(* Logix 5000 project; controller AMCI_3202_AOP_AOI_sample_RSLogix_V28 vendor 1 type 14 code 92 rev 28.11; software revision 28.00; part 2 of 3 *)
(* tags used below, declared in another part *)
   Manual_Move_CW_occurring : BOOL;
(* AMCI_3202_AOP_Manual_Move_CW, continued *)

ROUTINE Logic   (* ladder *)
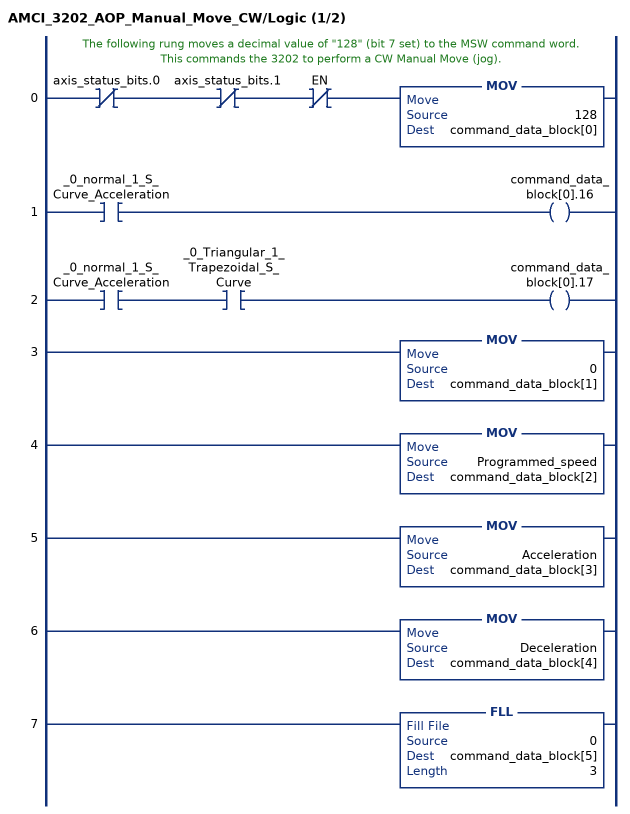
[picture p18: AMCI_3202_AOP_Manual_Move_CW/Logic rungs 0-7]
   // The following rung moves a decimal value of "128" (bit 7 set) to the MSW command word.  This commands the 3202 to perform a CW Manual Move (jog).
   0: XIO(axis_status_bits.0)XIO(axis_status_bits.1)XIO(EN)MOV(128,command_data_block[0]);
   1: XIC(_0_normal_1_S_Curve_Acceleration)OTE(command_data_block[0].16);
   2: XIC(_0_normal_1_S_Curve_Acceleration)XIC(_0_Triangular_1_Trapezoidal_S_Curve)OTE(command_data_block[0].17);
   3: MOV(0,command_data_block[1]);
   4: MOV(Programmed_speed,command_data_block[2]);
   5: MOV(Acceleration,command_data_block[3]);
   6: MOV(Deceleration,command_data_block[4]);
   7: FLL(0,command_data_block[5],3);
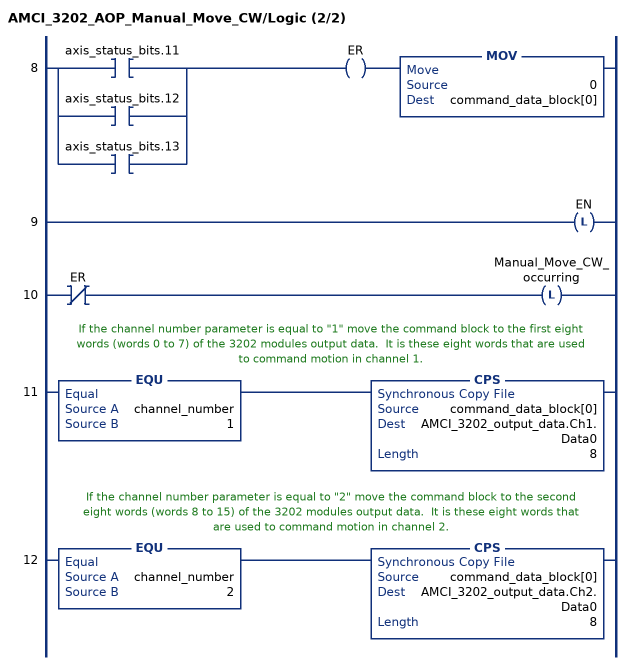
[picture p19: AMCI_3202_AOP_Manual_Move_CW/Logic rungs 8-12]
   8: [XIC(axis_status_bits.11) ,XIC(axis_status_bits.12) ,XIC(axis_status_bits.13) ]OTE(ER)MOV(0,command_data_block[0]);
   9: OTL(EN);
   10: XIO(ER)OTL(Manual_Move_CW_occurring);
   // If the channel number parameter is equal to "1" move the command block to the first eight words (words 0 to 7) of the 3202 modules output data.  It is these eight words that are used to command motion in channel 1.
   11: EQU(channel_number,1)CPS(command_data_block[0],AMCI_3202_output_data.Ch1.Data0,8);
   // If the channel number parameter is equal to "2" move the command block to the second eight words (words 8 to 15) of the 3202 modules output data.  It is these eight words that are used to command motion in channel 2.
   12: EQU(channel_number,2)CPS(command_data_block[0],AMCI_3202_output_data.Ch2.Data0,8);
END_ROUTINE
END_ADD_ON_INSTRUCTION

ADD_ON_INSTRUCTION AMCI_3202_AOP_Preset   (* revision 1.0, vendor AMCI, ExecuteEnableInFalse *)
VAR_INPUT
   axis_status_bits : INT; {required}
   channel_number : INT; {required}
   Target_Position : DINT; {required}
END_VAR
VAR_IN_OUT
   AMCI_3202_output_data : AM:1756_3202:O:0; {required}
END_VAR
VAR_OUTPUT
   EN : BOOL; {access Read Only, visible}
   ER : BOOL; {access Read Only, visible}
END_VAR
VAR
   command_data_block : DINT[8]; {access None}
END_VAR

ROUTINE EnableInFalse   (* ladder *)
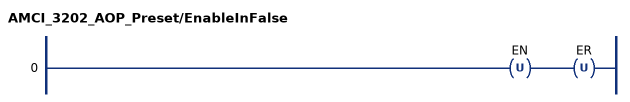
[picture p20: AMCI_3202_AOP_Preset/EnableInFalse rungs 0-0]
   0: OTU(EN)OTU(ER);
END_ROUTINE

ROUTINE Logic   (* ladder *)
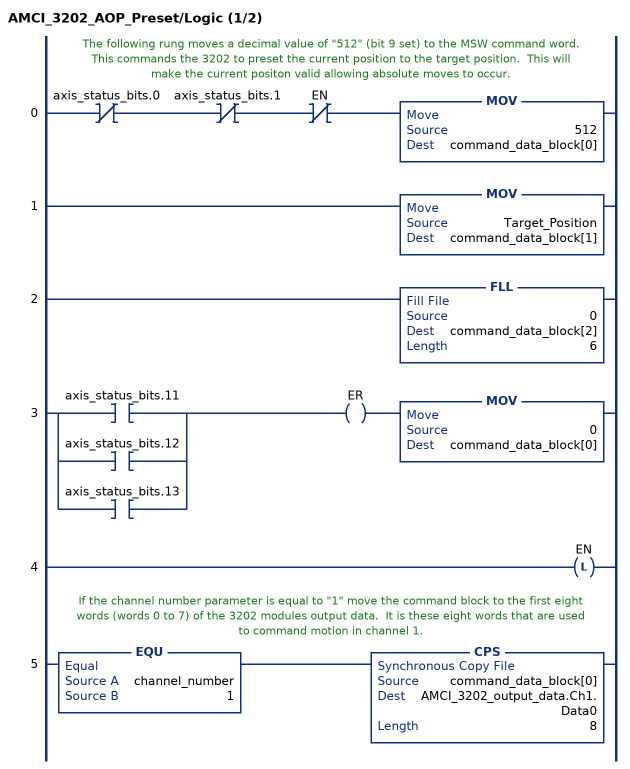
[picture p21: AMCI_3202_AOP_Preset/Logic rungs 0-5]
   // The following rung moves a decimal value of "512" (bit 9 set) to the MSW command word.  This commands the 3202 to preset the current position to the target position.  This will make the current positon valid allowing absolute moves to occur.
   0: XIO(axis_status_bits.0)XIO(axis_status_bits.1)XIO(EN)MOV(512,command_data_block[0]);
   1: MOV(Target_Position,command_data_block[1]);
   2: FLL(0,command_data_block[2],6);
   3: [XIC(axis_status_bits.11) ,XIC(axis_status_bits.12) ,XIC(axis_status_bits.13) ]OTE(ER)MOV(0,command_data_block[0]);
   4: OTL(EN);
   // If the channel number parameter is equal to "1" move the command block to the first eight words (words 0 to 7) of the 3202 modules output data.  It is these eight words that are used to command motion in channel 1.
   5: EQU(channel_number,1)CPS(command_data_block[0],AMCI_3202_output_data.Ch1.Data0,8);
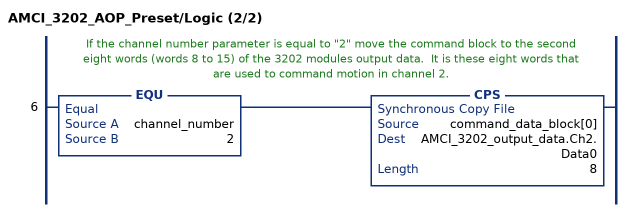
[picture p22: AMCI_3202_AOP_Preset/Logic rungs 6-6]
   // If the channel number parameter is equal to "2" move the command block to the second eight words (words 8 to 15) of the 3202 modules output data.  It is these eight words that are used to command motion in channel 2.
   6: EQU(channel_number,2)CPS(command_data_block[0],AMCI_3202_output_data.Ch2.Data0,8);
END_ROUTINE
END_ADD_ON_INSTRUCTION

ADD_ON_INSTRUCTION AMCI_3202_AOP_Preset_Encoder   (* revision 1.0, vendor AMCI, ExecuteEnableInFalse *)
VAR_INPUT
   axis_status_bits : INT; {required}
   channel_number : INT; {required}
   Target_Position : DINT; {required}
END_VAR
VAR_IN_OUT
   AMCI_3202_output_data : AM:1756_3202:O:0; {required}
END_VAR
VAR_OUTPUT
   EN : BOOL; {access Read Only, visible}
   ER : BOOL; {access Read Only, visible}
END_VAR
VAR
   command_data_block : DINT[8]; {access None}
END_VAR

ROUTINE EnableInFalse   (* ladder *)
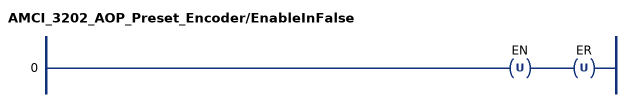
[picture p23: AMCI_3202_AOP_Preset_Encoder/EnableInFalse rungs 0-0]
   0: OTU(EN)OTU(ER);
END_ROUTINE

ROUTINE Logic   (* ladder *)
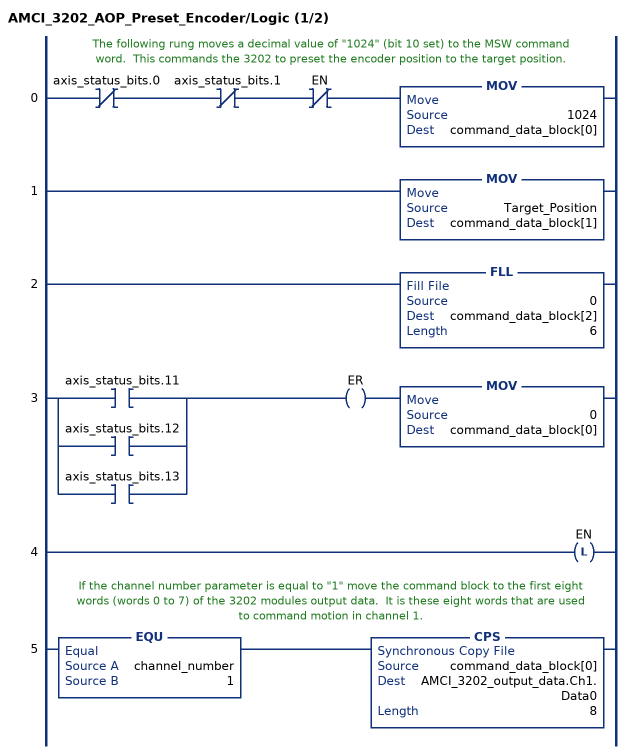
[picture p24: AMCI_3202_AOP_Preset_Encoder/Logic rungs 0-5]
   // The following rung moves a decimal value of "1024" (bit 10 set) to the MSW command word.  This commands the 3202 to preset the encoder position to the target position.
   0: XIO(axis_status_bits.0)XIO(axis_status_bits.1)XIO(EN)MOV(1024,command_data_block[0]);
   1: MOV(Target_Position,command_data_block[1]);
   2: FLL(0,command_data_block[2],6);
   3: [XIC(axis_status_bits.11) ,XIC(axis_status_bits.12) ,XIC(axis_status_bits.13) ]OTE(ER)MOV(0,command_data_block[0]);
   4: OTL(EN);
   // If the channel number parameter is equal to "1" move the command block to the first eight words (words 0 to 7) of the 3202 modules output data.  It is these eight words that are used to command motion in channel 1.
   5: EQU(channel_number,1)CPS(command_data_block[0],AMCI_3202_output_data.Ch1.Data0,8);
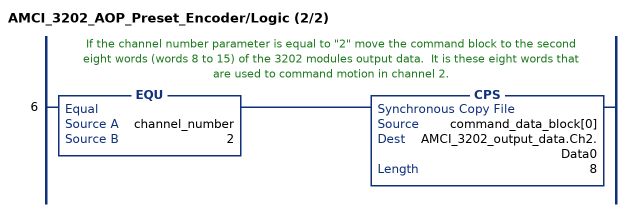
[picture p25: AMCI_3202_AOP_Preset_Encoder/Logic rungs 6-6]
   // If the channel number parameter is equal to "2" move the command block to the second eight words (words 8 to 15) of the 3202 modules output data.  It is these eight words that are used to command motion in channel 2.
   6: EQU(channel_number,2)CPS(command_data_block[0],AMCI_3202_output_data.Ch2.Data0,8);
END_ROUTINE
END_ADD_ON_INSTRUCTION

ADD_ON_INSTRUCTION AMCI_3202_AOP_Relative_Move   (* revision 1.0, vendor AMCI, ExecuteEnableInFalse *)
VAR_INPUT
   axis_status_bits : INT; {required}
   channel_number : INT; {required}
   _0_normal_1_S_Curve_Acceleration : BOOL;
   _0_Triangular_1_Trapezoidal_S_Curve : BOOL;
   _0_Target_Position_1_Encoder_Move : BOOL;
   Target_Position : DINT; {required}
   Programmed_speed : DINT; {required}
   Acceleration : DINT; {required}
   Deceleration : DINT; {required}
END_VAR
VAR_IN_OUT
   AMCI_3202_output_data : AM:1756_3202:O:0; {required}
END_VAR
VAR_OUTPUT
   EN : BOOL; {access Read Only, visible}
   ER : BOOL; {access Read Only, visible}
END_VAR
VAR
   command_data_block : DINT[8]; {access None}
END_VAR

ROUTINE EnableInFalse   (* ladder *)
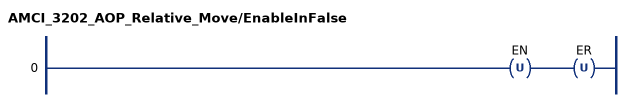
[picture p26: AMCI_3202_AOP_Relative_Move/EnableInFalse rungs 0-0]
   0: OTU(EN)OTU(ER);
END_ROUTINE

ROUTINE Logic   (* ladder *)
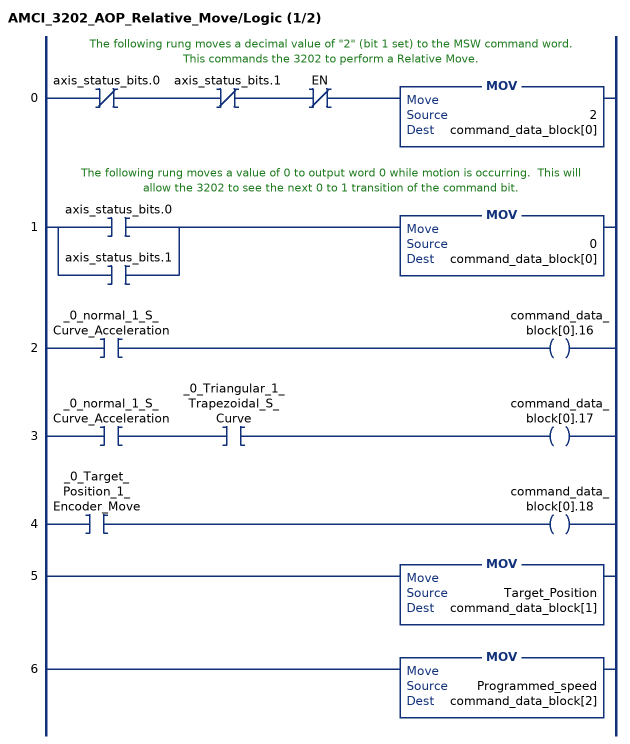
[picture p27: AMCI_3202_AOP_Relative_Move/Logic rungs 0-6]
   // The following rung moves a decimal value of "2" (bit 1 set) to the MSW command word.  This commands the 3202 to perform a Relative Move.
   0: XIO(axis_status_bits.0)XIO(axis_status_bits.1)XIO(EN)MOV(2,command_data_block[0]);
   // The following rung moves a value of 0 to output word 0 while motion is occurring.  This will allow the 3202 to see the next 0 to 1 transition of the command bit.
   1: [XIC(axis_status_bits.0) ,XIC(axis_status_bits.1) ]MOV(0,command_data_block[0]);
   2: XIC(_0_normal_1_S_Curve_Acceleration)OTE(command_data_block[0].16);
   3: XIC(_0_normal_1_S_Curve_Acceleration)XIC(_0_Triangular_1_Trapezoidal_S_Curve)OTE(command_data_block[0].17);
   4: XIC(_0_Target_Position_1_Encoder_Move)OTE(command_data_block[0].18);
   5: MOV(Target_Position,command_data_block[1]);
   6: MOV(Programmed_speed,command_data_block[2]);
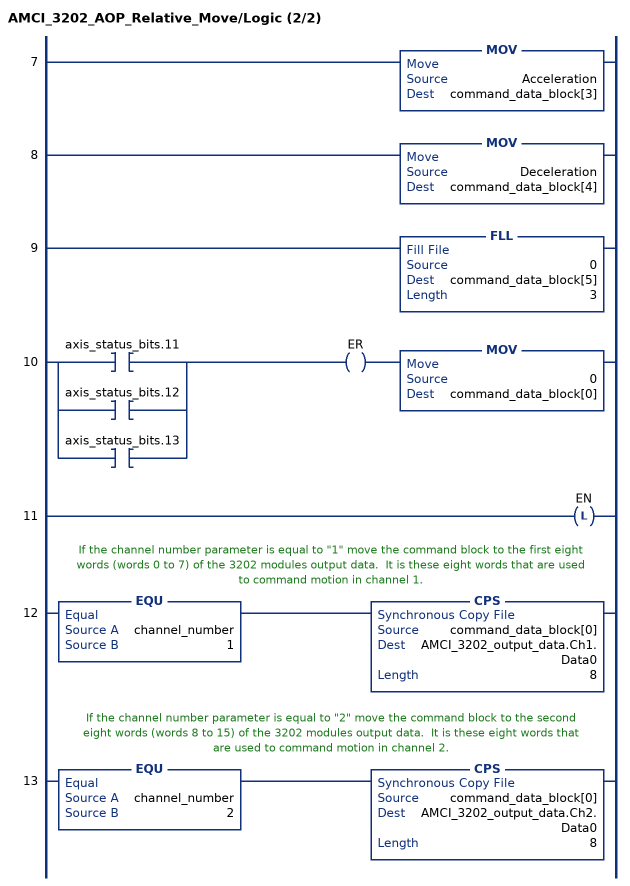
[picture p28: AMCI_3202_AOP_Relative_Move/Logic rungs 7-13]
   7: MOV(Acceleration,command_data_block[3]);
   8: MOV(Deceleration,command_data_block[4]);
   9: FLL(0,command_data_block[5],3);
   10: [XIC(axis_status_bits.11) ,XIC(axis_status_bits.12) ,XIC(axis_status_bits.13) ]OTE(ER)MOV(0,command_data_block[0]);
   11: OTL(EN);
   // If the channel number parameter is equal to "1" move the command block to the first eight words (words 0 to 7) of the 3202 modules output data.  It is these eight words that are used to command motion in channel 1.
   12: EQU(channel_number,1)CPS(command_data_block[0],AMCI_3202_output_data.Ch1.Data0,8);
   // If the channel number parameter is equal to "2" move the command block to the second eight words (words 8 to 15) of the 3202 modules output data.  It is these eight words that are used to command motion in channel 2.
   13: EQU(channel_number,2)CPS(command_data_block[0],AMCI_3202_output_data.Ch2.Data0,8);
END_ROUTINE
END_ADD_ON_INSTRUCTION

ADD_ON_INSTRUCTION AMCI_3202_AOP_Reset_Errors   (* revision 1.0, vendor AMCI, ExecuteEnableInFalse *)
VAR_INPUT
   axis_status_bits : INT; {required}
   channel_number : INT; {required}
END_VAR
VAR_OUTPUT
   EN : BOOL; {access Read Only, visible}
END_VAR
VAR_IN_OUT
   AMCI_3202_output_data : AM:1756_3202:O:0; {required}
END_VAR
VAR
   command_data_block : DINT[8]; {access None}
END_VAR

ROUTINE EnableInFalse   (* ladder *)
END_ROUTINE

ROUTINE Logic   (* ladder *)
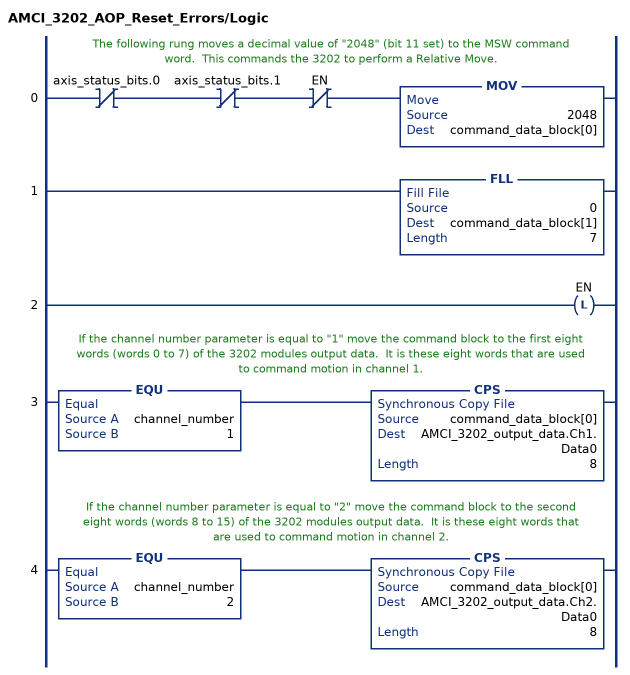
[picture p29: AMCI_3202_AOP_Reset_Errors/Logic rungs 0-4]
   // The following rung moves a decimal value of "2048" (bit 11 set) to the MSW command word.  This commands the 3202 to perform a Relative Move.
   0: XIO(axis_status_bits.0)XIO(axis_status_bits.1)XIO(EN)MOV(2048,command_data_block[0]);
   1: FLL(0,command_data_block[1],7);
   2: OTL(EN);
   // If the channel number parameter is equal to "1" move the command block to the first eight words (words 0 to 7) of the 3202 modules output data.  It is these eight words that are used to command motion in channel 1.
   3: EQU(channel_number,1)CPS(command_data_block[0],AMCI_3202_output_data.Ch1.Data0,8);
   // If the channel number parameter is equal to "2" move the command block to the second eight words (words 8 to 15) of the 3202 modules output data.  It is these eight words that are used to command motion in channel 2.
   4: EQU(channel_number,2)CPS(command_data_block[0],AMCI_3202_output_data.Ch2.Data0,8);
END_ROUTINE
END_ADD_ON_INSTRUCTION

ADD_ON_INSTRUCTION AMCI_3202_AOP_Resume   (* revision 1.0, vendor AMCI, ExecuteEnableInFalse *)
VAR_INPUT
   channel_number : INT; {required}
END_VAR
VAR_IN_OUT
   AMCI_3202_output_data : AM:1756_3202:O:0; {required}
END_VAR
VAR
   command_data_block : DINT[8]; {access None}
END_VAR

ROUTINE EnableInFalse   (* ladder *)
END_ROUTINE

ROUTINE Logic   (* ladder *)
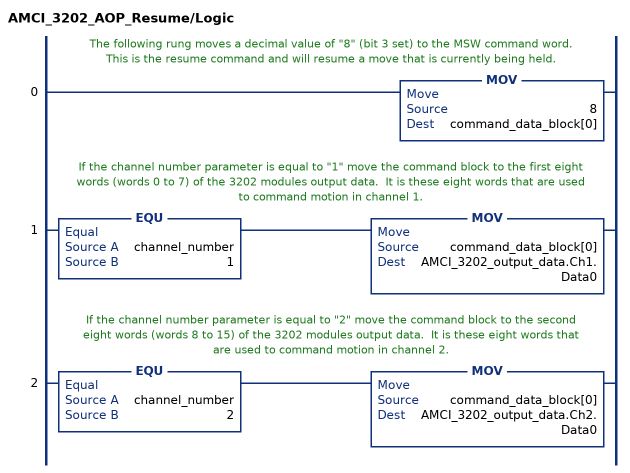
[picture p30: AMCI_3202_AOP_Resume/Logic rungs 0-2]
   // The following rung moves a decimal value of "8" (bit 3 set) to the MSW command word.  This is the resume command and will resume a move that is currently being held.
   0: MOV(8,command_data_block[0]);
   // If the channel number parameter is equal to "1" move the command block to the first eight words (words 0 to 7) of the 3202 modules output data.  It is these eight words that are used to command motion in channel 1.
   1: EQU(channel_number,1)MOV(command_data_block[0],AMCI_3202_output_data.Ch1.Data0);
   // If the channel number parameter is equal to "2" move the command block to the second eight words (words 8 to 15) of the 3202 modules output data.  It is these eight words that are used to command motion in channel 2.
   2: EQU(channel_number,2)MOV(command_data_block[0],AMCI_3202_output_data.Ch2.Data0);
END_ROUTINE
END_ADD_ON_INSTRUCTION

ADD_ON_INSTRUCTION AMCI_3202_AOP_Run_Blend   (* revision 1.0, vendor AMCI, ExecuteEnableInFalse *)
VAR_INPUT
   axis_status_bits : INT; {required}
   channel_number : INT; {required}
   Direction_0_for_CW_1_for_CCW : BOOL; {required}
END_VAR
VAR_IN_OUT
   AMCI_3202_output_data : AM:1756_3202:O:0; {required}
END_VAR
VAR_OUTPUT
   EN : BOOL; {access Read Only, visible}
   ER : BOOL; {access Read Only, visible}
END_VAR
VAR
   command_data_block : DINT[8]; {access None}
END_VAR

ROUTINE EnableInFalse   (* ladder *)
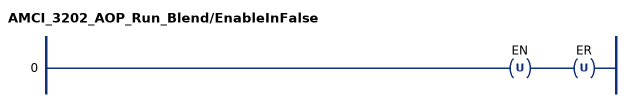
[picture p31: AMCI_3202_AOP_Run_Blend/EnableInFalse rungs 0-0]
   0: OTU(EN)OTU(ER);
END_ROUTINE

ROUTINE Logic   (* ladder *)
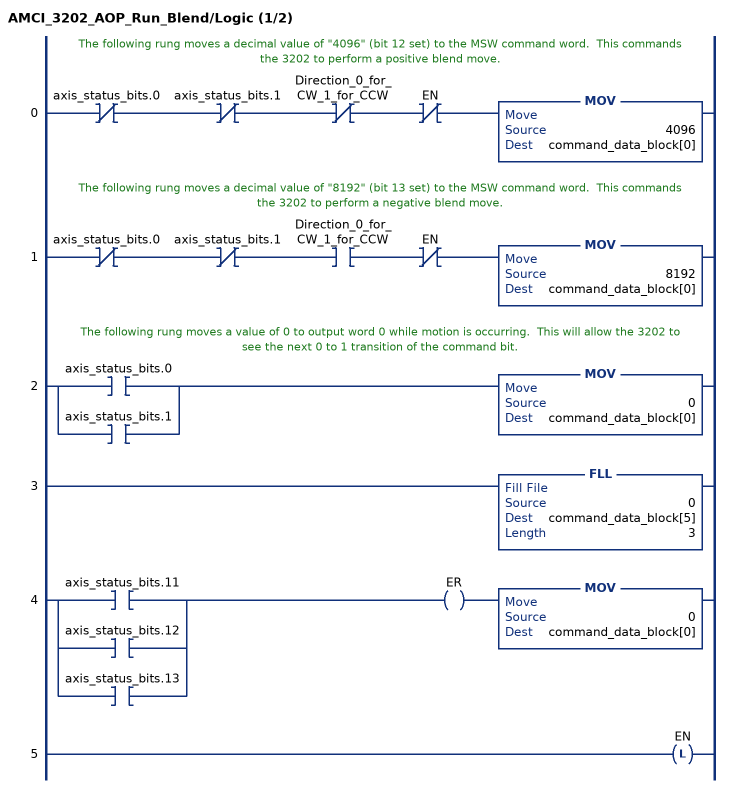
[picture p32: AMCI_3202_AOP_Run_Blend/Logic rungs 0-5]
   // The following rung moves a decimal value of "4096" (bit 12 set) to the MSW command word.  This commands the 3202 to perform a positive blend move.
   0: XIO(axis_status_bits.0)XIO(axis_status_bits.1)XIO(Direction_0_for_CW_1_for_CCW)XIO(EN)MOV(4096,command_data_block[0]);
   // The following rung moves a decimal value of "8192" (bit 13 set) to the MSW command word.  This commands the 3202 to perform a negative blend move.
   1: XIO(axis_status_bits.0)XIO(axis_status_bits.1)XIC(Direction_0_for_CW_1_for_CCW)XIO(EN)MOV(8192,command_data_block[0]);
   // The following rung moves a value of 0 to output word 0 while motion is occurring.  This will allow the 3202 to see the next 0 to 1 transition of the command bit.
   2: [XIC(axis_status_bits.0) ,XIC(axis_status_bits.1) ]MOV(0,command_data_block[0]);
   3: FLL(0,command_data_block[5],3);
   4: [XIC(axis_status_bits.11) ,XIC(axis_status_bits.12) ,XIC(axis_status_bits.13) ]OTE(ER)MOV(0,command_data_block[0]);
   5: OTL(EN);
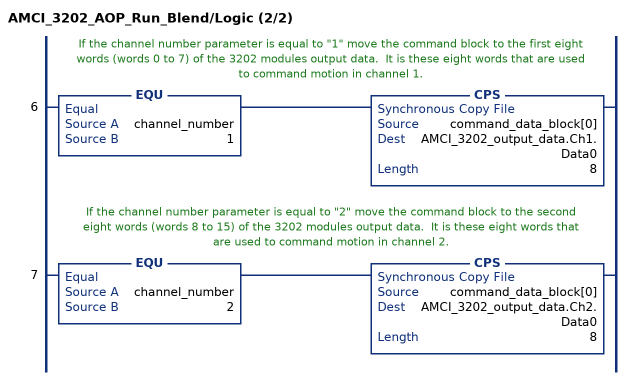
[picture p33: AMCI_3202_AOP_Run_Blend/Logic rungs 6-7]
   // If the channel number parameter is equal to "1" move the command block to the first eight words (words 0 to 7) of the 3202 modules output data.  It is these eight words that are used to command motion in channel 1.
   6: EQU(channel_number,1)CPS(command_data_block[0],AMCI_3202_output_data.Ch1.Data0,8);
   // If the channel number parameter is equal to "2" move the command block to the second eight words (words 8 to 15) of the 3202 modules output data.  It is these eight words that are used to command motion in channel 2.
   7: EQU(channel_number,2)CPS(command_data_block[0],AMCI_3202_output_data.Ch2.Data0,8);
END_ROUTINE
END_ADD_ON_INSTRUCTION

VAR_GLOBAL   (* controller tags *)
   blend_data_3202_ch1 : DINT[52];
        [11]   // Segment 3 speed
        [13]   // Segment 4 length
        [15]   // Segment 4 Acceleration or Deceleration
        [17]   // Segment 5 speed
        [1]   // Number of Segments
        [3]   // Final Segment's Deceleration Value and Type
        [5]   // Segment 1 speed
        [7]   // Segment 2 length
        [9]   // Segment 2 Acceleration or Deceleration
        [10]   // Segment 3 length
        [12]   // Segment 3 Acceleration or Deceleration
        [14]   // Segment 4 speed
        [16]   // Segment 5 length
        [18]   // Segment 5 Acceleraiton or Deceleration
        [0]   // channel number (1 or 2)
        [2]   // Acceleration Type
        [4]   // Segment 1 length
        [6]   // Segment 1 Acceleration or Deceleration
        [8]   // Segment 2 speed
   blend_data_3202_ch2 : DINT[52];
        [4]   // Segment 1 length
        [14]   // Segment 4 speed
        [6]   // Segment 1 Acceleration or Deceleration
        [17]   // Segment 5 speed
        [11]   // Segment 3 speed
        [15]   // Segment 4 Acceleration or Deceleration
        [1]   // Number of Segments
        [13]   // Segment 4 length
        [3]   // Final Segment's Deceleration Value and Type
        [16]   // Segment 5 length
        [5]   // Segment 1 speed
        [9]   // Segment 2 Acceleration or Deceleration
        [0]   // channel number (1 or 2)
        [7]   // Segment 2 length
        [12]   // Segment 3 Acceleration or Deceleration
        [2]   // Acceleration Type
        [10]   // Segment 3 length
        [18]   // Segment 5 Acceleraiton or Deceleration
        [8]   // Segment 2 speed
   blend_message_3202_ch1 : MESSAGE;
        .DN   // set when blend data has been programmed
        MessageParameters(ServiceCode := 16#004c, LocalElement := blend_data_3202_ch1[0], ...)
   blend_message_3202_ch2 : MESSAGE;
        .DN   // set when blend data has been programmed
        MessageParameters(ServiceCode := 16#004c, LocalElement := blend_data_3202_ch2[0], ...)
   blend_run_3202 : DINT[8] := ([0] := 4096);
        [0]   // command word to run blend profile CW
   buffered_3202_data : DINT[16];
        [8].13   // set when AMCI 3202 ch 2 has a configuration error
        [8].31   // AMCI 3202 ch 2 mode bit 1=config mode 0=command mode
        [8].0   // set when AMCI 3202 ch 2 CW motion is occurring
        [0].0   // set when AMCI 3202 ch 1 CW motion is occurring
        [0].1   // set when AMCI 3202 ch 1 CCW motion is occurring
        [0].7   // AMCI 3202 ch 1 move complete bit
        [8].1   // set when AMCI 3202 ch 2 CCW motion is occurring
        [0].28   // set when AMCI 3202 ch 1 is disabled
        [8].28   // set when AMCI 3202 ch 2 is disabled
        [0].10   // AMCI 3202 ch 1 position invalid bit
        [0].13   // set when AMCI 3202 ch 1 has a configuration error
        [0].31   // AMCI 3202 ch 1 mode bit 1=config mode 0=command mode
   comment : INT;
        .1   // comment coil for version rung
   run_3202_ch1 : INT;   // 1=Relative move 2=CW Manual Move 3=CCW Manual Move 4=Reset Errors 5=Home CW 6=Preset 7=Program Blend 8=Run Blend CW
   run_3202_ch2 : INT;   // 1=Relative move 2=CW Manual Move 3=CCW Manual Move 4=Reset Errors 5=Home CW 6=Preset 7=Program Blend 8=Run Blend CW
END_VAR

PROGRAM MainProgram   (* main routine MainRoutine *)
VAR
   AMCI_3202_ch1_absolut_move_aoi : AMCI_3202_AOP_Absolute_Move;
   AMCI_3202_ch1_config_AOI : AMCI_3202_AOP_Configure;
   AMCI_3202_ch1_hold_aoi : AMCI_3202_AOP_Hold;
   AMCI_3202_ch1_home_CCW_AOI : AMCI_3202_AOP_Home_CCW;
   AMCI_3202_ch1_Home_CW_AOI : AMCI_3202_AOP_Home_CW;
   AMCI_3202_ch1_immediate_stop_aoi : AMCI_3202_AOP_Immediate_Stop;
   AMCI_3202_ch1_Manual_Move_CCW_AOI : AMCI_3202_AOP_Manual_Move_CCW;
   AMCI_3202_ch1_Manual_Move_CW_AOI : AMCI_3202_AOP_Manual_Move_CW;
   AMCI_3202_ch1_Preset_AOI : AMCI_3202_AOP_Preset;
   AMCI_3202_ch1_preset_encoder_aoi : AMCI_3202_AOP_Preset_Encoder;
   AMCI_3202_ch1_relative_move_AOI : AMCI_3202_AOP_Relative_Move;
   AMCI_3202_ch1_reset_errors_AOI : AMCI_3202_AOP_Reset_Errors;
   AMCI_3202_ch1_resume_aoi : AMCI_3202_AOP_Resume;
   AMCI_3202_ch1_run_blend_AOI : AMCI_3202_AOP_Run_Blend;
   AMCI_3202_ch2_absolut_move_aoi : AMCI_3202_AOP_Absolute_Move;
   AMCI_3202_ch2_config_AOI : AMCI_3202_AOP_Configure;
   AMCI_3202_ch2_hold_aoi : AMCI_3202_AOP_Hold;
   AMCI_3202_ch2_home_CCW_AOI : AMCI_3202_AOP_Home_CCW;
   AMCI_3202_ch2_Home_CW_AOI : AMCI_3202_AOP_Home_CW;
   AMCI_3202_ch2_immediate_stop_aoi : AMCI_3202_AOP_Immediate_Stop;
   AMCI_3202_ch2_Manual_Move_CCW_AOI : AMCI_3202_AOP_Manual_Move_CCW;
   AMCI_3202_ch2_Manual_Move_CW_AOI : AMCI_3202_AOP_Manual_Move_CW;
   AMCI_3202_ch2_Preset_AOI : AMCI_3202_AOP_Preset;
   AMCI_3202_ch2_relative_move_AOI : AMCI_3202_AOP_Relative_Move;
   AMCI_3202_ch2_reset_errors_AOI : AMCI_3202_AOP_Reset_Errors;
   AMCI_3202_ch2_resume_aoi : AMCI_3202_AOP_Resume;
   AMCI_3202_ch2_run_blend_AOI : AMCI_3202_AOP_Run_Blend;
END_VAR

ROUTINE channel_1_3202   (* ladder *)
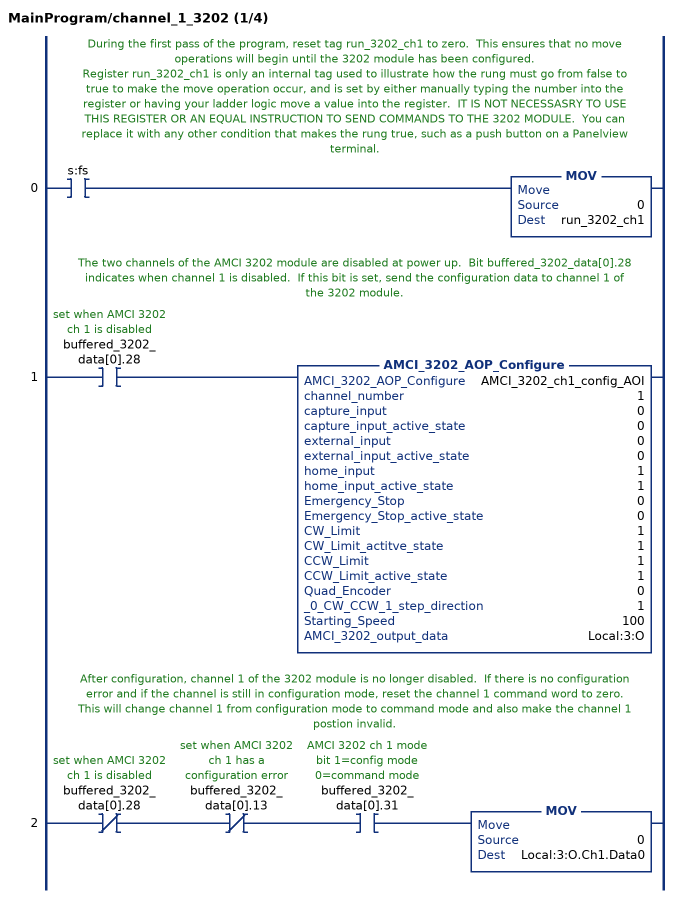
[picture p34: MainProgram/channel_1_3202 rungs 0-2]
   // During the first pass of the program, reset tag run_3202_ch1 to zero.  This ensures that no move operations will begin until the 3202 module has been configured.
   // Register run_3202_ch1 is only an internal tag used to illustrate how the rung must go from false to true to make the move operation occur, and is set by either manually typing the number into the register or having your ladder logic move a value into the register.  IT IS NOT NECESSASRY TO USE THIS REGISTER OR AN EQUAL INSTRUCTION TO SEND COMMANDS TO THE 3202 MODULE.  You can replace it with any other condition that makes the rung true, such as a push button on a Panelview terminal.
   0: XIC(s:fs)MOV(0,run_3202_ch1);
   // The two channels of the AMCI 3202 module are disabled at power up.  Bit buffered_3202_data[0].28 indicates when channel 1 is disabled.  If this bit is set, send the configuration data to channel 1 of the 3202 module.
   1: XIC(buffered_3202_data[0].28)AMCI_3202_AOP_Configure(AMCI_3202_ch1_config_AOI,1,0,0,0,0,1,1,0,0,1,1,1,1,0,1,100,Local:3:O);
   // After configuration, channel 1 of the 3202 module is no longer disabled.  If there is no configuration error and if the channel is still in configuration mode, reset the channel 1 command word to zero.  This will change channel 1 from configuration mode to command mode and also make the channel 1 postion invalid.
   2: XIO(buffered_3202_data[0].28)XIO(buffered_3202_data[0].13)XIC(buffered_3202_data[0].31)MOV(0,Local:3:O.Ch1.Data0);
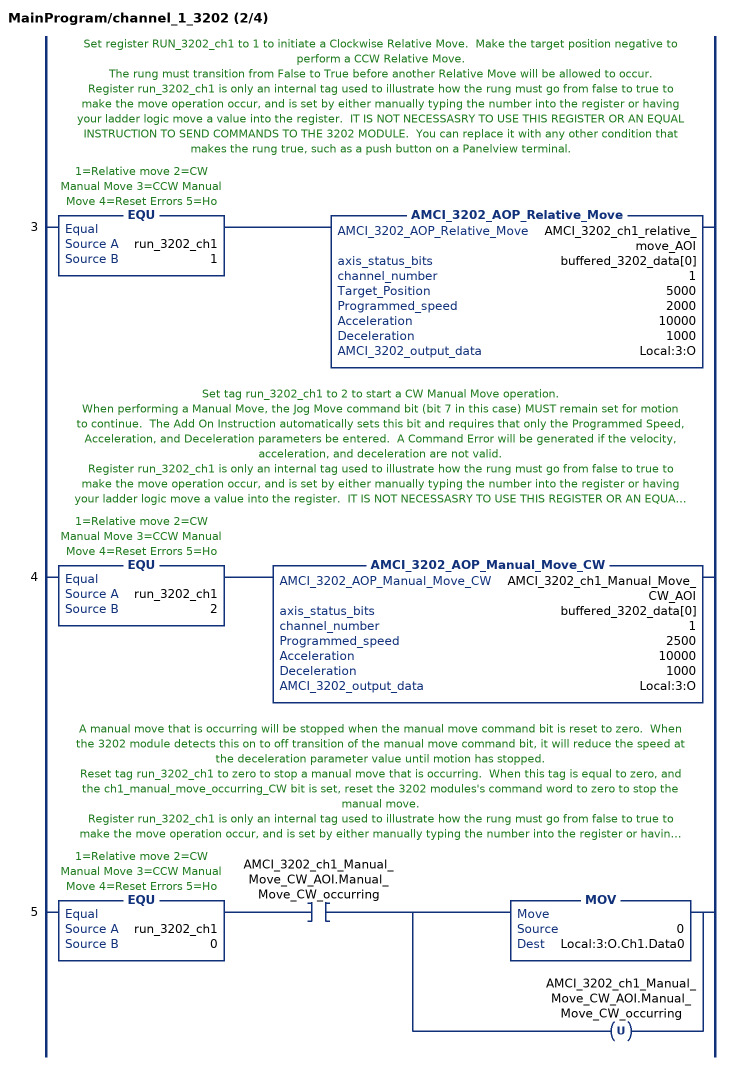
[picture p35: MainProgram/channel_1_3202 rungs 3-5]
   // Set register RUN_3202_ch1 to 1 to initiate a Clockwise Relative Move.  Make the target position negative to perform a CCW Relative Move.
   // The rung must transition from False to True before another Relative Move will be allowed to occur.
   // Register run_3202_ch1 is only an internal tag used to illustrate how the rung must go from false to true to make the move operation occur, and is set by either manually typing the number into the register or having your ladder logic move a value into the register.  IT IS NOT NECESSASRY TO USE THIS REGISTER OR AN EQUAL INSTRUCTION TO SEND COMMANDS TO THE 3202 MODULE.  You can replace it with any other condition that makes the rung true, such as a push button on a Panelview terminal.
   3: EQU(run_3202_ch1,1)AMCI_3202_AOP_Relative_Move(AMCI_3202_ch1_relative_move_AOI,buffered_3202_data[0],1,5000,2000,10000,1000,Local:3:O);
   // Set tag run_3202_ch1 to 2 to start a CW Manual Move operation.
   // When performing a Manual Move, the Jog Move command bit (bit 7 in this case) MUST remain set for motion to continue.  The Add On Instruction automatically sets this bit and requires that only the Programmed Speed, Acceleration, and Deceleration parameters be entered.  A Command Error will be generated if the velocity, acceleration, and deceleration are not valid.
   // Register run_3202_ch1 is only an internal tag used to illustrate how the rung must go from false to true to make the move operation occur, and is set by either manually typing the number into the register or having your ladder logic move a value into the register.  IT IS NOT NECESSASRY TO USE THIS REGISTER OR AN EQUAL INSTRUCTION TO SEND COMMANDS TO THE 3202 MODULE.  You can replace it with any other condition that makes the rung true, such as a push button on a Panelview terminal.
   4: EQU(run_3202_ch1,2)AMCI_3202_AOP_Manual_Move_CW(AMCI_3202_ch1_Manual_Move_CW_AOI,buffered_3202_data[0],1,2500,10000,1000,Local:3:O);
   // A manual move that is occurring will be stopped when the manual move command bit is reset to zero.  When the 3202 module detects this on to off transition of the manual move command bit, it will reduce the speed at the deceleration parameter value until motion has stopped.
   // Reset tag run_3202_ch1 to zero to stop a manual move that is occurring.  When this tag is equal to zero, and the ch1_manual_move_occurring_CW bit is set, reset the 3202 modules's command word to zero to stop the manual move.
   // Register run_3202_ch1 is only an internal tag used to illustrate how the rung must go from false to true to make the move operation occur, and is set by either manually typing the number into the register or having your ladder logic move a value into the register.  IT IS NOT NECESSASRY TO USE THIS REGISTER OR AN EQUAL INSTRUCTION TO SEND COMMANDS TO THE 3202 MODULE.  You can replace it with any other condition that makes the rung true, such as a push button on a Panelview terminal.
   5: EQU(run_3202_ch1,0)XIC(AMCI_3202_ch1_Manual_Move_CW_AOI.Manual_Move_CW_occurring)[MOV(0,Local:3:O.Ch1.Data0) ,OTU(AMCI_3202_ch1_Manual_Move_CW_AOI.Manual_Move_CW_occurring) ];
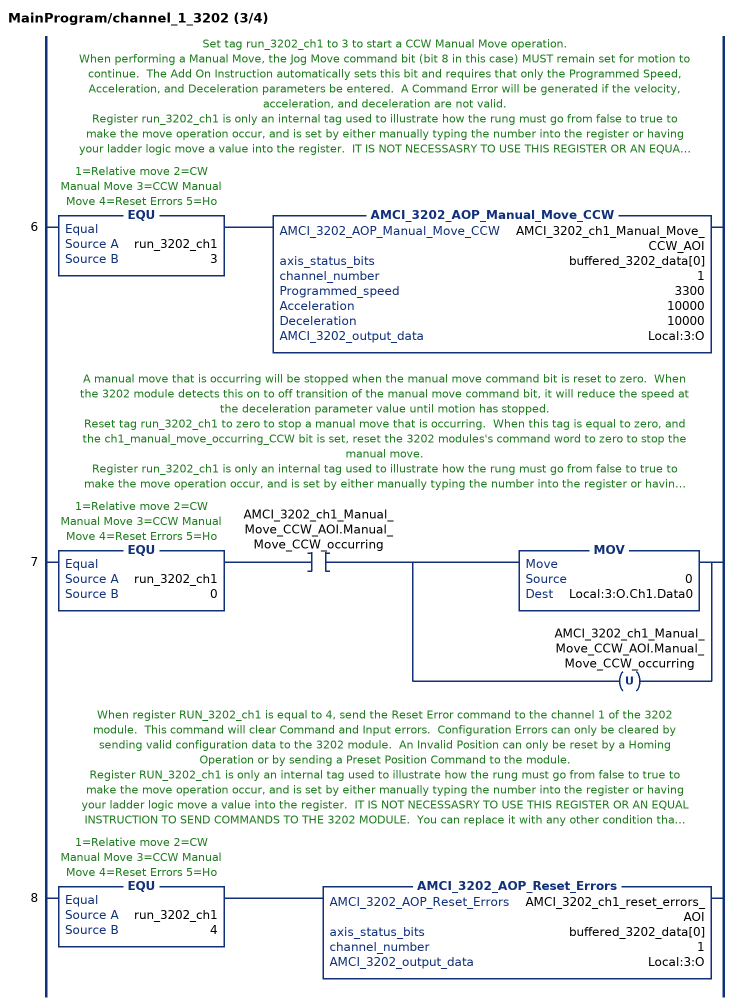
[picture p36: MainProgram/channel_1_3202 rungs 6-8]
   // Set tag run_3202_ch1 to 3 to start a CCW Manual Move operation.
   // When performing a Manual Move, the Jog Move command bit (bit 8 in this case) MUST remain set for motion to continue.  The Add On Instruction automatically sets this bit and requires that only the Programmed Speed, Acceleration, and Deceleration parameters be entered.  A Command Error will be generated if the velocity, acceleration, and deceleration are not valid.
   // Register run_3202_ch1 is only an internal tag used to illustrate how the rung must go from false to true to make the move operation occur, and is set by either manually typing the number into the register or having your ladder logic move a value into the register.  IT IS NOT NECESSASRY TO USE THIS REGISTER OR AN EQUAL INSTRUCTION TO SEND COMMANDS TO THE 3202 MODULE.  You can replace it with any other condition that makes the rung true, such as a push button on a Panelview terminal.
   6: EQU(run_3202_ch1,3)AMCI_3202_AOP_Manual_Move_CCW(AMCI_3202_ch1_Manual_Move_CCW_AOI,buffered_3202_data[0],1,3300,10000,10000,Local:3:O);
   // A manual move that is occurring will be stopped when the manual move command bit is reset to zero.  When the 3202 module detects this on to off transition of the manual move command bit, it will reduce the speed at the deceleration parameter value until motion has stopped.
   // Reset tag run_3202_ch1 to zero to stop a manual move that is occurring.  When this tag is equal to zero, and the ch1_manual_move_occurring_CCW bit is set, reset the 3202 modules's command word to zero to stop the manual move.
   // Register run_3202_ch1 is only an internal tag used to illustrate how the rung must go from false to true to make the move operation occur, and is set by either manually typing the number into the register or having your ladder logic move a value into the register.  IT IS NOT NECESSASRY TO USE THIS REGISTER OR AN EQUAL INSTRUCTION TO SEND COMMANDS TO THE 3202 MODULE.  You can replace it with any other condition that makes the rung true, such as a push button on a Panelview terminal.
   7: EQU(run_3202_ch1,0)XIC(AMCI_3202_ch1_Manual_Move_CCW_AOI.Manual_Move_CCW_occurring)[MOV(0,Local:3:O.Ch1.Data0) ,OTU(AMCI_3202_ch1_Manual_Move_CCW_AOI.Manual_Move_CCW_occurring) ];
   // When register RUN_3202_ch1 is equal to 4, send the Reset Error command to the channel 1 of the 3202 module.  This command will clear Command and Input errors.  Configuration Errors can only be cleared by sending valid configuration data to the 3202 module.  An Invalid Position can only be reset by a Homing Operation or by sending a Preset Position Command to the module.
   // Register RUN_3202_ch1 is only an internal tag used to illustrate how the rung must go from false to true to make the move operation occur, and is set by either manually typing the number into the register or having your ladder logic move a value into the register.  IT IS NOT NECESSASRY TO USE THIS REGISTER OR AN EQUAL INSTRUCTION TO SEND COMMANDS TO THE 3202 MODULE.  You can replace it with any other condition that makes the rung true, such as a push button on a Panelview terminal.
   8: EQU(run_3202_ch1,4)AMCI_3202_AOP_Reset_Errors(AMCI_3202_ch1_reset_errors_AOI,buffered_3202_data[0],1,Local:3:O);
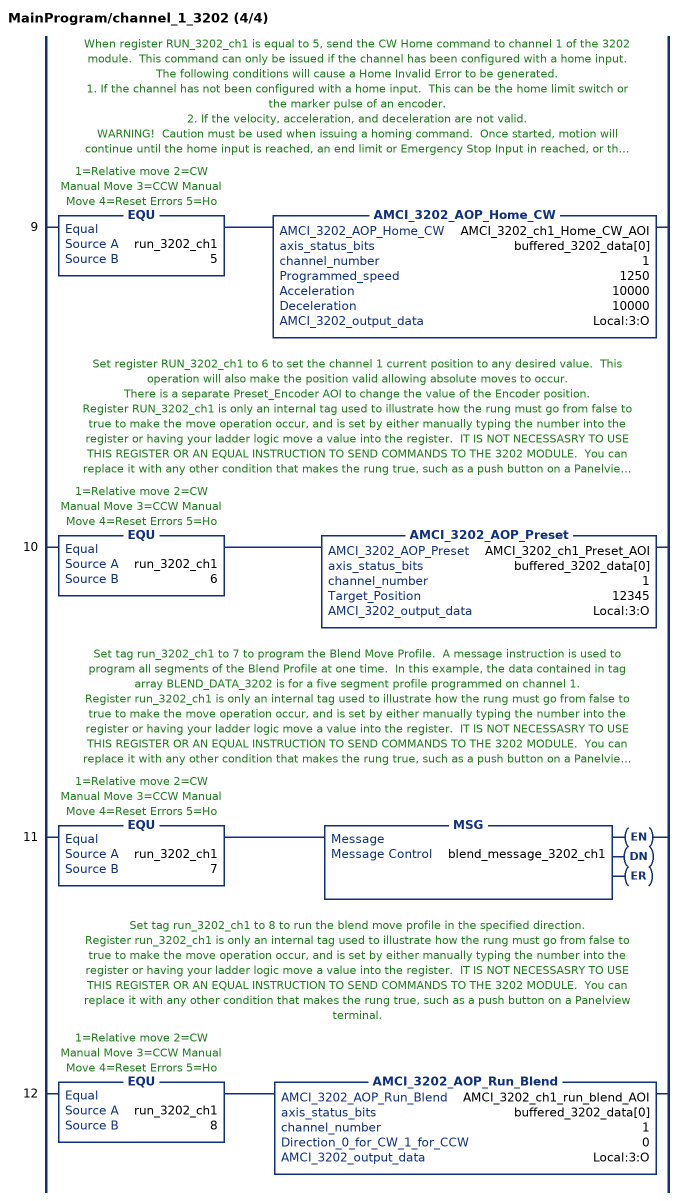
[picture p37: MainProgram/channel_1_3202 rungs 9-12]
   // When register RUN_3202_ch1 is equal to 5, send the CW Home command to channel 1 of the 3202 module.  This command can only be issued if the channel has been configured with a home input.  The following conditions will cause a Home Invalid Error to be generated.
   // 1. If the channel has not been configured with a home input.  This can be the home limit switch or the marker pulse of an encoder.
   // 2. If the velocity, acceleration, and deceleration are not valid.
   // WARNING!  Caution must be used when issuing a homing command.  Once started, motion will continue until the home input is reached, an end limit or Emergency Stop Input in reached, or the Immediate Stop Command is issued.  Resetting the command word to zero WILL NOT STOP a home operation.
   // Register RUN_3202_ch1 is only an internal tag used to illustrate how the rung must go from false to true to make the move operation occur, and is set by either manually typing the number into the register or having your ladder logic move a value into the register.  IT IS NOT NECESSASRY TO USE THIS REGISTER OR AN EQUAL INSTRUCTION TO SEND COMMANDS TO THE 3202 MODULE.  You can replace it with any other condition that makes the rung true, such as a push button on a Panelview terminal.
   9: EQU(run_3202_ch1,5)AMCI_3202_AOP_Home_CW(AMCI_3202_ch1_Home_CW_AOI,buffered_3202_data[0],1,1250,10000,10000,Local:3:O);
   // Set register RUN_3202_ch1 to 6 to set the channel 1 current position to any desired value.  This operation will also make the position valid allowing absolute moves to occur.
   // There is a separate Preset_Encoder AOI to change the value of the Encoder position.
   // Register RUN_3202_ch1 is only an internal tag used to illustrate how the rung must go from false to true to make the move operation occur, and is set by either manually typing the number into the register or having your ladder logic move a value into the register.  IT IS NOT NECESSASRY TO USE THIS REGISTER OR AN EQUAL INSTRUCTION TO SEND COMMANDS TO THE 3202 MODULE.  You can replace it with any other condition that makes the rung true, such as a push button on a Panelview terminal.
   10: EQU(run_3202_ch1,6)AMCI_3202_AOP_Preset(AMCI_3202_ch1_Preset_AOI,buffered_3202_data[0],1,12345,Local:3:O);
   // Set tag run_3202_ch1 to 7 to program the Blend Move Profile.  A message instruction is used to program all segments of the Blend Profile at one time.  In this example, the data contained in tag array BLEND_DATA_3202 is for a five segment profile programmed on channel 1.
   // Register run_3202_ch1 is only an internal tag used to illustrate how the rung must go from false to true to make the move operation occur, and is set by either manually typing the number into the register or having your ladder logic move a value into the register.  IT IS NOT NECESSASRY TO USE THIS REGISTER OR AN EQUAL INSTRUCTION TO SEND COMMANDS TO THE 3202 MODULE.  You can replace it with any other condition that makes the rung true, such as a push button on a Panelview terminal.
   11: EQU(run_3202_ch1,7)MSG(blend_message_3202_ch1);
   // Set tag run_3202_ch1 to 8 to run the blend move profile in the specified direction.
   // Register run_3202_ch1 is only an internal tag used to illustrate how the rung must go from false to true to make the move operation occur, and is set by either manually typing the number into the register or having your ladder logic move a value into the register.  IT IS NOT NECESSASRY TO USE THIS REGISTER OR AN EQUAL INSTRUCTION TO SEND COMMANDS TO THE 3202 MODULE.  You can replace it with any other condition that makes the rung true, such as a push button on a Panelview terminal.
   12: EQU(run_3202_ch1,8)AMCI_3202_AOP_Run_Blend(AMCI_3202_ch1_run_blend_AOI,buffered_3202_data[0],1,0,Local:3:O);
END_ROUTINE
